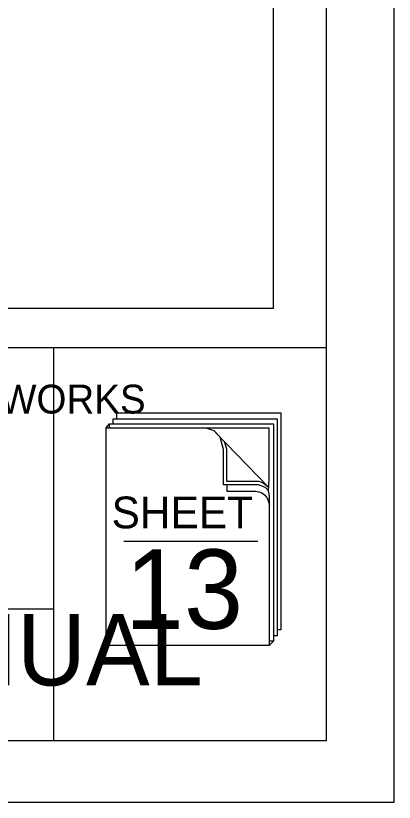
# Model space of a CAD drawing. Extents: x 2147138 to 2147698, y 2147153 to 2147515.
# Drawn here: x 2147650 to 2147697.7, y 2147152.8 to 2147251.8 of the extents above; entities that cross this region are included whole.
import ezdxf

# ---------------------------------------------------------------- set-up
doc = ezdxf.new("R2010")
doc.units = 0
for name, color, linetype in [('BORDER', 7, 'Continuous'), ('CONSTRUCTION_CLASS', 7, 'Continuous'), ('LEVEL_2', 7, 'Continuous'), ('PATTERN_CLASS', 7, 'Continuous')]:
    doc.layers.add(name, color=color, linetype=linetype)

msp = doc.modelspace()

# ---------------------------------------------------------------- linework, layer by layer
at = {"layer": 'BORDER'}
for p, q in [((2147675.154, 2147199.367), (2147681.786, 2147192.536)), ((2147681.194, 2147192.973), (2147681.843, 2147192.492))]:
    msp.add_line(p, q, dxfattribs=at)
for points in [[(2147662.246, 2147200.433), (2147662.246, 2147201.078), (2147682.892, 2147201.078), (2147682.892, 2147173.742), (2147682.423, 2147173.742)], [(2147662.716, 2147201.078), (2147662.716, 2147201.852), (2147683.36, 2147201.852), (2147683.36, 2147174.516), (2147682.892, 2147174.516)], [(2147681.875, 2147199.925), (2147675.598, 2147199.925), (2147673.977, 2147199.918), (2147661.307, 2147199.918), (2147661.777, 2147200.433), (2147682.423, 2147200.433), (2147682.423, 2147173.097), (2147681.955, 2147172.582), (2147681.955, 2147189.408), (2147681.955, 2147191.34), (2147681.829, 2147192.02), (2147681.875, 2147193.457), (2147681.875, 2147199.925)], [(2147661.777, 2147199.918), (2147661.777, 2147200.433), (2147682.423, 2147200.433), (2147682.423, 2147173.097), (2147681.955, 2147173.097)], [(2147681.194, 2147192.973), (2147680.622, 2147193.182), (2147676.569, 2147193.182), (2147676.569, 2147197.275), (2147676.273, 2147198.214)], [(2147676.57, 2147192.744), (2147676.57, 2147191.962), (2147680.176, 2147191.962), (2147680.603, 2147191.894), (2147680.956, 2147191.751), (2147681.294, 2147191.514), (2147681.574, 2147191.238), (2147681.727, 2147190.939), (2147681.955, 2147190.234), (2147681.947, 2147191.38), (2147681.829, 2147192.02), (2147681.426, 2147192.439), (2147680.548, 2147192.762), (2147676.57, 2147192.744)], [(2147663.57, 2147185.7), (2147680.452, 2147185.7)]]:
    msp.add_lwpolyline(points, dxfattribs=at)
for points in [[(2147681.875, 2147199.925), (2147675.598, 2147199.925), (2147673.977, 2147199.918), (2147661.307, 2147199.918), (2147661.777, 2147200.433), (2147682.423, 2147200.433), (2147682.423, 2147173.097), (2147681.955, 2147172.582), (2147681.955, 2147189.408), (2147681.955, 2147191.34), (2147681.829, 2147192.02), (2147681.875, 2147193.457)], [(2147661.307, 2147172.582), (2147681.955, 2147172.582), (2147681.955, 2147189.408), (2147681.955, 2147190.474), (2147681.955, 2147191.34), (2147681.955, 2147191.34), (2147681.829, 2147192.02), (2147681.426, 2147192.439), (2147680.548, 2147192.762), (2147676.147, 2147192.762), (2147676.147, 2147197.209), (2147675.72, 2147198.785), (2147674.962, 2147199.562), (2147673.977, 2147199.918), (2147661.307, 2147199.918)], [(2147676.57, 2147192.744), (2147676.57, 2147191.962), (2147680.176, 2147191.962), (2147680.603, 2147191.894), (2147680.956, 2147191.751), (2147681.294, 2147191.514), (2147681.574, 2147191.238), (2147681.727, 2147190.939), (2147681.955, 2147190.234), (2147681.947, 2147191.38), (2147681.829, 2147192.02), (2147681.426, 2147192.439), (2147680.548, 2147192.762)]]:
    msp.add_lwpolyline(points, close=True, dxfattribs=at)
at = {"layer": 'CONSTRUCTION_CLASS'}
for p, q in [((2147697.658, 2147152.807), (2147697.658, 2147515.078)), ((2147689.056, 2147507.94), (2147689.056, 2147160.521)), ((2147689.056, 2147160.521), (2147160.204, 2147160.521)), ((2147137.785, 2147152.807), (2147697.658, 2147152.807))]:
    msp.add_line(p, q, dxfattribs=at)
at = {"layer": 'LEVEL_2'}
for points in [[(2147689.075, 2147210.003), (2147556.761, 2147210.003)], [(2147654.75, 2147160.521), (2147654.75, 2147210.003)], [(2147654.75, 2147177.099), (2147556.761, 2147177.099)]]:
    msp.add_lwpolyline(points, dxfattribs=at)
at = {"layer": 'PATTERN_CLASS'}
for p, q in [((2147682.438, 2147215.016), (2147682.438, 2147344.122)), ((2147558.253, 2147215.016), (2147682.438, 2147215.016))]:
    msp.add_line(p, q, dxfattribs=at)

# ---------------------------------------------------------------- texts
at = {"layer": 'BORDER'}
for s, height, p in [('DEPARTMENT OF PUBLIC WORKS', 3.63, (2147586.232, 2147201.754)), ('SHEET', 4, (2147662.039, 2147187.296)), ('13', 10, (2147663.729, 2147174.64)), ('ENGINEERING STANDARDS MANUAL', 9, (2147458.211, 2147167.52))]:
    msp.add_text(s, height=height, dxfattribs=at).set_placement(p)

doc.saveas('drawing.dxf')
